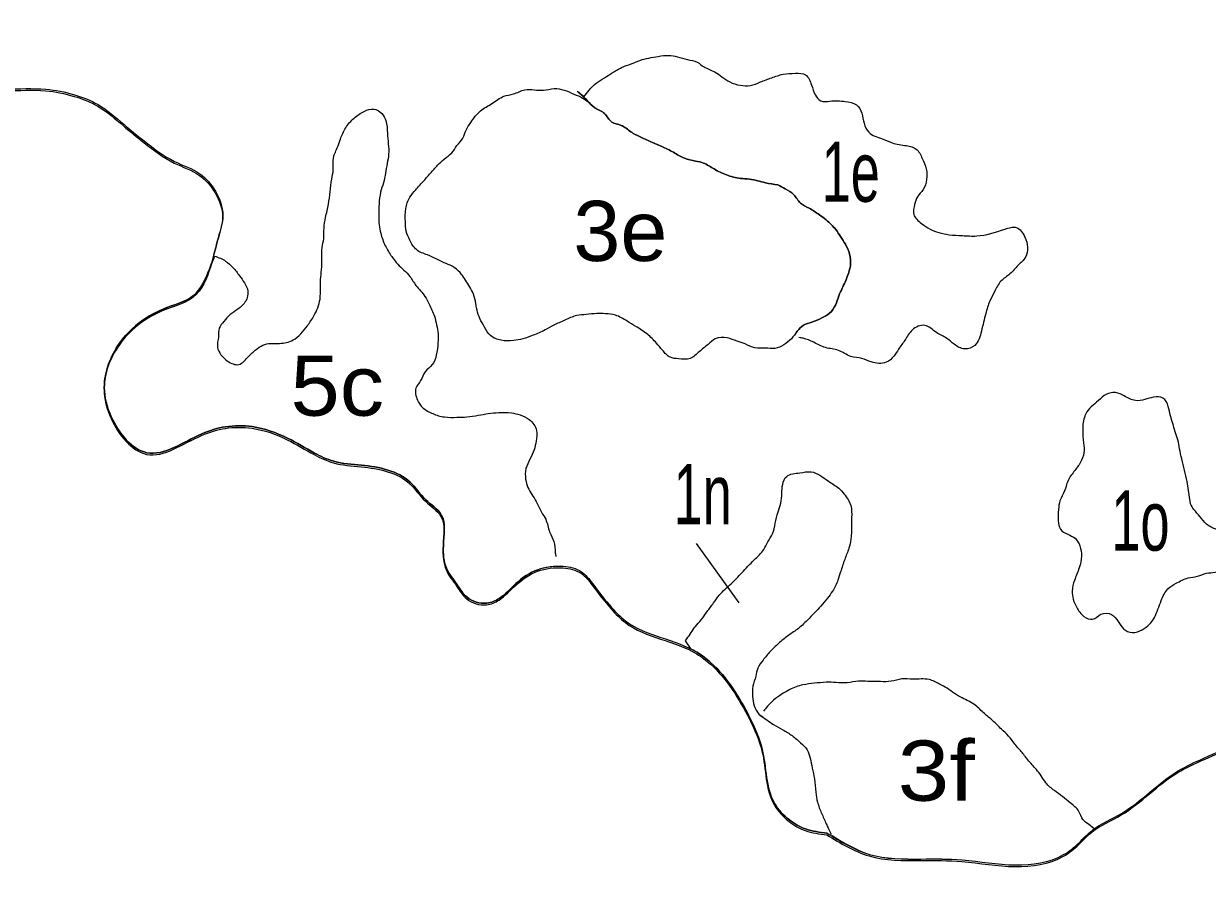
# Model space of a CAD drawing. Extents: x 854879 to 917879, y 8541948 to 8631048.
# Drawn here: x 875201 to 882670, y 8594058 to 8599480 of the extents above; entities that cross this region are included whole.
import ezdxf
from ezdxf.enums import TextEntityAlignment as Align

# ---------------------------------------------------------------- set-up
doc = ezdxf.new("R2010")
doc.units = 0
doc.header["$LTSCALE"] = 150
for name, color, linetype, lineweight in [('12', 7, 'Continuous', 13), ('40', 7, 'Continuous', 13), ('50', 7, 'Continuous', 13), ('59', 7, 'Continuous', 13)]:
    doc.layers.add(name, color=color, linetype=linetype, lineweight=lineweight)

msp = doc.modelspace()

# ---------------------------------------------------------------- linework, layer by layer
at = {"layer": '12'}
for points in [[(871540.4, 8601616.3), (871630.5, 8601735.3), (871725.4, 8601821.2), (871819.8, 8601853.5), (871913.6, 8601811.8), (872009.1, 8601696.2), (872090.3, 8601675.1), (872352.9, 8601741.6), (872559.5, 8601800.9), (872768.1, 8601811.8), (872925.4, 8601774.7), (873100.7, 8601750.2), (873246.8, 8601606.1), (873273.5, 8601468.2), (873319, 8601169.5), (873340.7, 8601036.7), (873373.3, 8600995.6), (873443.9, 8600926.1), (873503.6, 8600780.3), (873522.1, 8600586.3), (873508.5, 8600492.1), (873474.4, 8600380.2), (873420, 8600283.8), (873381.1, 8600200.1), (873357.3, 8600100.8), (873362, 8600065.1), (873409.5, 8599978), (873462.5, 8599931.6), (873479.8, 8599877.9), (873496.2, 8599735), (873544.2, 8599691.2), (873656.2, 8599700.4), (873722.2, 8599694.7), (873826.1, 8599653), (873995.5, 8599546.9), (874109.6, 8599510.2), (874211.1, 8599483.8), (874337.8, 8599434.2), (874512.3, 8599325.6), (874651.2, 8599230), (875018.4, 8599061), (875087.1, 8599057.8), (875338.8, 8599055.6), (875519.1, 8599020.8), (875668.6, 8598958.3), (875830.2, 8598834.4), (875958.9, 8598728.8), (876150.9, 8598599.6), (876310.4, 8598521.6), (876408.6, 8598411.1), (876455.5, 8598257.7), (876426.2, 8598117.8), (876378.7, 8597942.2), (876270.1, 8597752), (876109.2, 8597679.5), (875976.3, 8597614.4), (875804.4, 8597452.8), (875707.7, 8597173.2), (875751.7, 8596986.7), (875975.9, 8596760.3), (876322.9, 8596879.6), (876473.4, 8596924.1), (876641.3, 8596925.2), (876864.4, 8596851.8), (877033.9, 8596758.4), (877155.5, 8596706.4), (877330.8, 8596681.8), (877637.5, 8596574.6), (877735.6, 8596464.1), (877833.9, 8596368.8), (877847.3, 8596172.4), (877866.3, 8596032), (877934, 8595926.8), (877996.9, 8595847.2), (878121.1, 8595810.4), (878200.3, 8595840.3), (878305.4, 8595933.7), (878443.6, 8596021.7), (878604, 8596043.2), (878718.1, 8596009.1), (878788.7, 8595934.5), (878909.3, 8595783), (878997.5, 8595698), (879448.4, 8595500.2), (879534.2, 8595435.7), (879780.2, 8595089.3), (879859.7, 8594887.2), (879937.8, 8594544.8), (880031, 8594442), (880132.2, 8594385), (880269.2, 8594358.3)], [(880269.2, 8594358.3), (880535.6, 8594224.4), (880861.5, 8594195), (881121.5, 8594189.3), (881457.6, 8594157.3), (881761.8, 8594222.4), (881859.5, 8594297.7), (881942, 8594375.7), (882126.8, 8594483.1), (882484.4, 8594751.5), (882646, 8594831.1), (882871.6, 8594938), (882987.3, 8595023.2), (883140.6, 8595266), (883304.2, 8595304.8), (883658.6, 8594880.1), (883852.4, 8594668.9), (883929.4, 8594497.2), (884079.3, 8594240.6), (884294.2, 8593873.6), (884407.5, 8593755), (884857.3, 8593206.9), (885015.1, 8592973.1), (885120.2, 8592803.6), (885156.3, 8592627.4), (885225.8, 8592471.1), (885469.6, 8592391.7), (885591.8, 8592372.4)]]:
    msp.add_spline(points, degree=3, dxfattribs=at)
at = {"layer": '40'}
for p, q in [((878781.6, 8598969.1), (878693.6, 8599054.5)), ((876373.7, 8597930.1), (876406, 8598012.1)), ((882563.2, 8596448.4), (882543.7, 8596587.9)), ((879413.8, 8595529.9), (879377.1, 8595582.4))]:
    msp.add_line(p, q, dxfattribs=at)
for points in [[(879960.2, 8598461.7), (880006.7, 8598436.8), (880060.7, 8598399.8), (880102.5, 8598347.2), (880156.7, 8598314.2), (880222.4, 8598273), (880264.8, 8598240.3), (880326, 8598179.3), (880356.2, 8598134.9), (880386.2, 8598086.6), (880412, 8598026.4), (880417.7, 8597950.8), (880400, 8597887.7), (880366.2, 8597809), (880345.1, 8597761.8), (880323.6, 8597702.8), (880286.6, 8597652), (880238.4, 8597621.3), (880174.6, 8597594.9), (880122.8, 8597576.2), (880082.3, 8597537.4), (880045.4, 8597490.6), (879997, 8597452), (879941.2, 8597429.4), (879882.1, 8597430.8), (879815.2, 8597432.3), (879752.9, 8597457.5), (879702.2, 8597474.6), (879639.8, 8597495.9), (879564.8, 8597489.6), (879520.4, 8597454.9), (879463.9, 8597408.5), (879407.5, 8597366.1), (879332.6, 8597363.8), (879281.6, 8597372.9), (879231.7, 8597417.7), (879193.7, 8597462.3), (879136.3, 8597519.2), (879062.9, 8597568.5), (879008.7, 8597601.5), (878935, 8597639), (878872.2, 8597648.3), (878817.1, 8597649.6), (878750, 8597643.2), (878690.7, 8597636.6), (878614.9, 8597606.5), (878547.1, 8597576.3), (878491, 8597545.8), (878415.1, 8597511.8), (878351.4, 8597489.4), (878292, 8597478.8), (878213.3, 8597480.6), (878147.2, 8597509.9), (878109.3, 8597562.4), (878079.5, 8597618.7), (878061.4, 8597670.7), (878051.2, 8597726.6), (878033.3, 8597786.6), (878007.1, 8597830.8), (877954.2, 8597907.5), (877904.2, 8597948.3), (877853.6, 8597969.4), (877803.1, 8597994.3), (877748.7, 8598019.4), (877678.8, 8598052.8), (877637.3, 8598113.3), (877615.3, 8598169.4), (877609.2, 8598229.1), (877611.7, 8598312.5), (877637.5, 8598383.4), (877674.3, 8598430.2), (877719.2, 8598480.8), (877768.1, 8598535.3), (877812.9, 8598585.9), (877853.5, 8598624.7), (877901.9, 8598663.3), (877934.8, 8598710.3), (877971.7, 8598757.1), (877992.9, 8598808.2), (878021.9, 8598855.2), (878083.2, 8598929.3), (878155.5, 8598975.3), (878231.7, 8599021.3), (878291.2, 8599035.8), (878362.9, 8599062), (878481, 8599059.3), (878548.3, 8599069.7), (878611, 8599060.3), (878673.3, 8599035.1), (878727.7, 8599010), (878781.6, 8598969.1)], [(878693.6, 8599054.5), (878712.8, 8599038.2), (878758.7, 8598993.4), (878804.7, 8598948.7), (878866.6, 8598911.5), (878912.3, 8598858.8), (878970.8, 8598837.7), (879032.6, 8598796.5), (879094.6, 8598763.4), (879168.5, 8598729.9), (879226.8, 8598704.8), (879300.5, 8598667.3), (879370.3, 8598630), (879440.7, 8598612.5), (879491.5, 8598599.4), (879557.4, 8598562.2), (879635.1, 8598524.7), (879725, 8598502.8), (879780, 8598497.6), (879881.8, 8598475.4), (879960.2, 8598461.7)], [(876406, 8598012.1), (876475.1, 8597980.8), (876521.2, 8597940.1), (876563, 8597887.5), (876593.2, 8597843.1), (876615.2, 8597790.9), (876601.5, 8597727.7), (876552.7, 8597677.2), (876504.4, 8597642.5), (876463.8, 8597599.8), (876434.9, 8597556.7), (876429.3, 8597501.2), (876423.5, 8597437.8), (876445.7, 8597389.7), (876487.8, 8597349), (876558.1, 8597327.5), (876622.7, 8597381.7), (876675.3, 8597428.1), (876723.4, 8597454.8), (876814.2, 8597460.7), (876901.5, 8597482.6), (876949.9, 8597521.2), (876990.8, 8597571.9), (877032.1, 8597634.5), (877070.7, 8597740.9), (877072.8, 8597812.3), (877074.4, 8597863.9), (877080.2, 8597927.3), (877082.3, 8597998.8), (877084.4, 8598066.3), (877093.9, 8598121.7), (877095.9, 8598189.1), (877105.8, 8598256.4), (877124, 8598339.4), (877134.3, 8598418.6), (877144.5, 8598497.8), (877154.2, 8598557.2), (877156.4, 8598632.6), (877182.2, 8598703.5), (877199.3, 8598750.8), (877233, 8598821.5), (877286, 8598883.9), (877350.3, 8598926.1), (877409.8, 8598940.6), (877460.2, 8598911.7), (877486.5, 8598867.4), (877495.9, 8598787.8), (877501.8, 8598720.1), (877503.8, 8598656.5), (877494.2, 8598597.1), (877470.8, 8598474.5), (877453.3, 8598415.4), (877443.3, 8598344.1), (877441.1, 8598272.7), (877443.2, 8598209.1), (877453.5, 8598157.2), (877482.6, 8598077.1), (877523.9, 8598008.6), (877561.8, 8597960.1), (877600.1, 8597923.5), (877638.3, 8597882.9), (877676, 8597826.4), (877733.1, 8597757.6), (877759.2, 8597709.4), (877792.4, 8597633.1), (877806.5, 8597577.2), (877816.6, 8597521.4), (877815, 8597465.8), (877804.7, 8597386.6), (877779.3, 8597327.6), (877734.6, 8597281), (877705.4, 8597226), (877676.4, 8597179), (877686, 8597103.3), (877720, 8597054.9), (877781.9, 8597017.7), (877856.1, 8596996.2), (877934.8, 8596994.4), (877997.9, 8596996.9), (878069.2, 8597007.2), (878132.5, 8597017.7), (878199.7, 8597024.1), (878278.4, 8597022.3), (878333.2, 8597009.2), (878391.4, 8596980.1), (878436.6, 8596911.5), (878434.6, 8596844), (878421.1, 8596788.7), (878395.7, 8596729.7)], [(878587.7, 8596054.5), (878445.3, 8596032), (878307.1, 8595944), (878202, 8595850.6), (878122.8, 8595820.7), (877998.6, 8595857.5), (877935.7, 8595937.1), (877868.1, 8596042.2), (877849, 8596182.7), (877835.6, 8596379.1), (877737.3, 8596474.3), (877639.2, 8596584.8), (877332.5, 8596692.1), (877157.2, 8596716.6), (877035.6, 8596768.7), (876866.1, 8596862), (876643, 8596935.4), (876475.1, 8596934.4), (876324.6, 8596889.8), (875977.6, 8596770.6), (875753.4, 8596996.9), (875709.4, 8597183.4), (875806.1, 8597463), (875978, 8597624.7), (876110.9, 8597689.8), (876271.8, 8597762.3), (876373.7, 8597930.1)], [(882543.7, 8596587.9), (882526.2, 8596659.8), (882508.6, 8596731.7), (882494.8, 8596795.5), (882484.6, 8596851.3), (882466.5, 8596903.4), (882452.2, 8596955.3), (882437.9, 8597003.3), (882424, 8597063.2), (882390.1, 8597115.6), (882331.1, 8597120.9), (882275.5, 8597106.3), (882216.2, 8597099.7), (882146.2, 8597129.1), (882091.7, 8597150.2), (882020.2, 8597132), (881971.7, 8597089.4), (881927.2, 8597050.7), (881898.2, 8597003.7), (881883.8, 8596916.6), (881889.2, 8596833.1), (881891.2, 8596769.5), (881869.8, 8596710.4), (881828.6, 8596651.8), (881787.2, 8596585.2), (881769.8, 8596530), (881740.4, 8596467.1), (881730.9, 8596411.7), (881728.7, 8596340.2), (881742.9, 8596288.3), (881789.2, 8596255.5), (881835.8, 8596230.6), (881865.8, 8596182.2), (881875.8, 8596118.5), (881861.7, 8596043.3), (881831.8, 8595964.6), (881817.9, 8595897.3), (881824.3, 8595845.6), (881846.3, 8595793.4), (881891.9, 8595736.8), (881946.6, 8595719.7), (881998.7, 8595750.2), (882065.6, 8595748.7), (882107.6, 8595704.1), (882141.8, 8595659.6), (882196.2, 8595634.6), (882259.8, 8595653), (882336.9, 8595730.7), (882358.1, 8595781.8), (882379.5, 8595836.9), (882421.1, 8595911.4), (882473.3, 8595946), (882549.2, 8595980), (882608.6, 8595990.6), (882664.3, 8596009.2), (882719.7, 8596015.9), (882771.2, 8596026.6), (882834.4, 8596033.1), (882922.7, 8596086.7), (882963, 8596117.6), (882957, 8596181.3), (882891.4, 8596226.5), (882841, 8596251.4), (882786.2, 8596264.6), (882727.7, 8596285.8), (882665.7, 8596319), (882623.8, 8596367.6), (882585.7, 8596412.1), (882563.2, 8596448.4)], [(878395.7, 8596729.7), (878370.3, 8596670.7), (878368.3, 8596603.3), (878382.5, 8596551.3), (878435, 8596462.7), (878468.5, 8596394.4), (878494.7, 8596350.2), (878519.9, 8596270.2), (878545.7, 8596210), (878555.4, 8596138.3), (878558.8, 8596115.7)], [(879377.1, 8595582.4), (879386.1, 8595595.1), (879439.7, 8595673.3), (879476.4, 8595716.2), (879513.4, 8595767), (879554.4, 8595821.7), (879591.4, 8595872.4), (879664.4, 8595942.3), (879733.4, 8596012.2), (879810.7, 8596093.9), (879871.8, 8596160), (879896.8, 8596207.1), (879925.9, 8596258.1), (879943.7, 8596325.2), (879961.6, 8596396.3), (879979, 8596451.5), (879984.8, 8596514.9), (879990.4, 8596570.4), (880015.6, 8596621.4), (880099, 8596643.4), (880170.1, 8596649.7), (880224.6, 8596628.6), (880278.6, 8596591.6), (880344.2, 8596546.5), (880378.6, 8596509.9), (880419.8, 8596437.5), (880425.4, 8596361.9), (880423.9, 8596310.3), (880421.3, 8596223), (880407.8, 8596167.7), (880382, 8596096.8), (880356.1, 8596017.9), (880338.8, 8595966.7), (880305.1, 8595896), (880272.3, 8595853), (880231.4, 8595802.3), (880190.8, 8595759.5), (880146, 8595712.9), (880081.3, 8595654.8), (880020.9, 8595612.5), (879964.4, 8595566.1), (879911.7, 8595515.7), (879866.7, 8595461.1), (879833.7, 8595410.2), (879820.3, 8595358.8), (879802.7, 8595295.7), (879800.8, 8595232.2), (879810.8, 8595172.4), (879840.8, 8595120.1), (879890.9, 8595083.2), (879933.3, 8595054.4), (879991.5, 8595021.3), (880049.4, 8594984.3), (880103.3, 8594939.3), (880145.3, 8594894.7), (880163.4, 8594842.7), (880177.3, 8594778.8), (880191, 8594711), (880200.3, 8594627.3), (880210.2, 8594563.6), (880235.8, 8594495.5), (880265.2, 8594427.3), (880278.7, 8594398.2)], [(880271, 8594368.6), (880133.9, 8594395.3), (880032.7, 8594452.3), (879939.5, 8594555.1), (879861.4, 8594897.4), (879781.9, 8595099.6), (879535.9, 8595446), (879450.1, 8595510.5), (879413.8, 8595529.9)]]:
    msp.add_spline(points, degree=3, dxfattribs=at)
at = {"layer": '50'}
msp.add_line((881956.8, 8594395.5), (881919.8, 8594425.4), dxfattribs=at)
for points in [[(873761.7, 8599693.5), (873827.8, 8599663.2), (873997.2, 8599557.2), (874111.3, 8599520.5), (874212.8, 8599494.1), (874339.5, 8599444.5), (874514, 8599335.8), (874652.9, 8599240.3), (875020.1, 8599071.2), (875088.8, 8599068.1), (875340.5, 8599065.8), (875520.8, 8599031.1), (875670.2, 8598968.5), (875831.8, 8598844.7), (875960.6, 8598739), (876152.6, 8598609.8), (876312.1, 8598531.9), (876410.3, 8598421.4), (876457.2, 8598268), (876427.9, 8598128), (876380.4, 8597952.5), (876271.8, 8597762.3), (876110.9, 8597689.8), (875978, 8597624.7), (875806.1, 8597463), (875709.4, 8597183.4), (875753.4, 8596996.9), (875977.6, 8596770.6), (876324.6, 8596889.8), (876475.1, 8596934.4), (876643, 8596935.4), (876866.1, 8596862), (877035.6, 8596768.7), (877157.2, 8596716.6), (877332.5, 8596692.1), (877639.2, 8596584.8), (877737.3, 8596474.3), (877835.6, 8596379.1), (877849, 8596182.7), (877868.1, 8596042.2), (877935.7, 8595937.1), (877998.6, 8595857.5), (878122.8, 8595820.7), (878202, 8595850.6), (878307.1, 8595944), (878445.3, 8596032), (878605.7, 8596053.5), (878719.8, 8596019.3), (878790.3, 8595944.7), (878911, 8595793.2), (878999.2, 8595708.3), (879450.1, 8595510.5), (879535.9, 8595446), (879781.9, 8595099.6), (879861.4, 8594897.4), (879939.5, 8594555.1), (880032.7, 8594452.3), (880133.9, 8594395.3), (880271, 8594368.6)], [(878735.2, 8599017.1), (878768.6, 8599060.7), (878813.2, 8599103.4), (878865.5, 8599137.9), (878913.7, 8599168.6), (878973.8, 8599203), (879033.5, 8599225.5), (879089.4, 8599248.1), (879145, 8599262.7), (879204.4, 8599273.2), (879271.5, 8599279.7), (879326.4, 8599270.5), (879388.9, 8599253.2), (879451.4, 8599235.8), (879493.9, 8599207.1), (879563.8, 8599173.7), (879606.3, 8599144.9), (879656.5, 8599112), (879722.9, 8599090.7), (879785.8, 8599089.2), (879849.6, 8599111.6), (879921.2, 8599137.8), (879992.8, 8599160), (880071.8, 8599166.2), (880134.5, 8599156.8), (880172, 8599092.4), (880197.7, 8599028.2), (880232, 8598991.7), (880287.2, 8598990.5), (880385.6, 8598988.2), (880455.8, 8598966.8), (880489.7, 8598914.4), (880503.6, 8598850.5), (880533.4, 8598794.2), (880618.9, 8598752.6), (880681.1, 8598727.3), (880771.2, 8598709.4), (880833.6, 8598688.1), (880871.2, 8598627.7), (880896.9, 8598563.6), (880898.8, 8598496), (880877.2, 8598432.9), (880840.3, 8598386.1), (880823.2, 8598338.8), (880817.3, 8598275.4), (880866.9, 8598218.7), (880920.9, 8598181.7), (880975.4, 8598160.6), (881042, 8598147.2), (881124.6, 8598141.3), (881215.1, 8598139.3), (881393.7, 8598182.9), (881464.9, 8598193.2), (881518.2, 8598132.4), (881536, 8598068.4), (881522.3, 8598005.2), (881477.5, 8597954.6), (881424.7, 8597900.2), (881368.1, 8597853.8), (881326.7, 8597787.2), (881297.4, 8597728.3), (881271.4, 8597649.4), (881257.9, 8597594.2), (881244.5, 8597538.8), (881202.4, 8597448.4), (881138.7, 8597426.1), (881072.6, 8597455.4), (881026.4, 8597492.2), (880960.6, 8597529.4), (880887.1, 8597574.8), (880807.4, 8597544.8), (880762.2, 8597482.3), (880721, 8597423.6), (880692.2, 8597380.6), (880643.7, 8597342), (880549.3, 8597344.1), (880490.8, 8597365.3), (880420.3, 8597378.8), (880342.6, 8597416.3), (880260.4, 8597434.1), (880186.6, 8597467.6), (880120.3, 8597492.9), (880092.9, 8597497.5)], [(879960.2, 8598461.7), (879881.8, 8598475.4), (879780, 8598497.6), (879725, 8598502.8), (879635.1, 8598524.7), (879557.4, 8598562.2), (879491.5, 8598599.4), (879440.7, 8598612.5), (879370.3, 8598630), (879300.5, 8598667.3), (879226.8, 8598704.8), (879168.5, 8598729.9), (879094.6, 8598763.4), (879032.6, 8598796.5), (878970.8, 8598837.7), (878912.3, 8598858.8), (878866.6, 8598911.5), (878804.7, 8598948.7), (878758.7, 8598993.4), (878734.4, 8599017.9)], [(880066.3, 8597517), (880082.3, 8597537.4), (880122.8, 8597576.2), (880174.6, 8597594.9), (880238.4, 8597621.3), (880286.6, 8597652), (880323.6, 8597702.8), (880345.1, 8597761.8), (880366.2, 8597809), (880400, 8597887.7), (880417.7, 8597950.8), (880412, 8598026.4), (880386.2, 8598086.6), (880356.2, 8598134.9), (880326, 8598179.3), (880264.8, 8598240.3), (880222.4, 8598273), (880156.7, 8598314.2), (880102.5, 8598347.2), (880060.7, 8598399.8), (880006.7, 8598436.8), (879960.2, 8598461.7)], [(881919.8, 8594425.4), (881885.2, 8594454), (881859.2, 8594506.2), (881805.6, 8594559.1), (881755.6, 8594599.9), (881705.5, 8594636.8), (881651.8, 8594685.7), (881621.6, 8594730.1), (881591.3, 8594770.5), (881537.9, 8594831.3), (881496.2, 8594883.9), (881450.5, 8594936.6), (881416.3, 8594981), (881370.4, 8595025.8), (881316.8, 8595078.6), (881263, 8595123.5), (881205.5, 8595176.5), (881124.1, 8595222), (881073.8, 8595250.9), (881027.5, 8595283.8), (880981, 8595308.7), (880914.9, 8595338), (880812.5, 8595340.3), (880741.6, 8595341.9), (880674.2, 8595327.5), (880607.2, 8595325.1), (880528.5, 8595326.9), (880469.4, 8595328.2), (880398.2, 8595317.9), (880327.3, 8595319.5), (880264.3, 8595321), (880189.3, 8595314.7), (880118.1, 8595304.4), (880034.5, 8595274.6), (879970.3, 8595236.3), (879921.9, 8595197.7), (879868.9, 8595139.3)], [(880271, 8594368.6), (880537.3, 8594234.6), (880863.2, 8594205.2), (881123.2, 8594199.6), (881459.3, 8594167.5), (881763.5, 8594232.7), (881861.2, 8594308), (881943.7, 8594386), (882128.6, 8594493.3), (882486.1, 8594761.7), (882647.7, 8594841.3), (882873.2, 8594948.2), (882989, 8595033.5), (883142.3, 8595276.3), (883305.9, 8595315.1), (883660.3, 8594890.4), (883854.1, 8594679.1), (883931.1, 8594507.5), (884081, 8594250.8), (884295.9, 8593883.9), (884409.2, 8593765.3), (884859, 8593217.1), (885016.8, 8592983.3), (885121.9, 8592813.9), (885158, 8592637.6), (885227.5, 8592481.3), (885471.3, 8592402), (885593.5, 8592382.7)], [(879849.6, 8595113), (879890.9, 8595083.2), (879933.3, 8595054.4), (879991.5, 8595021.3), (880049.4, 8594984.3), (880103.3, 8594939.3), (880145.3, 8594894.7), (880163.4, 8594842.7), (880177.3, 8594778.8), (880191, 8594711), (880200.3, 8594627.3), (880210.2, 8594563.6), (880235.8, 8594495.5), (880265.2, 8594427.3), (880287.5, 8594379.1), (880296.2, 8594360)], [(880302.6, 8594352.6), (880537.3, 8594234.6), (880863.2, 8594205.2), (881123.2, 8594199.6), (881459.3, 8594167.5), (881763.5, 8594232.7), (881861.2, 8594308), (881943.7, 8594386), (881956.8, 8594395.5)]]:
    msp.add_spline(points, degree=3, dxfattribs=at)
at = {"layer": '59'}
msp.add_line((879443.7, 8596197), (879713.8, 8595823), dxfattribs=at)

# ---------------------------------------------------------------- texts
for s, width, p in [('1e', 0.65, (880420, 8598355.1)), ('3e', 1.05, (878965.9, 8597981.1)), ('5c', 1.1, (877179.5, 8597004.4)), ('1n', 0.65, (879485.2, 8596318.7)), ('1o', 0.65, (882248, 8596152.4)), ('3f', 1.15, (880960.1, 8594573.2))]:
    msp.add_text(s, height=380, dxfattribs=dict(at, width=width)).set_placement(p, align=Align.CENTER)

doc.saveas('drawing.dxf')
